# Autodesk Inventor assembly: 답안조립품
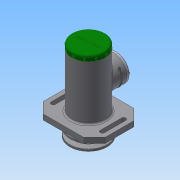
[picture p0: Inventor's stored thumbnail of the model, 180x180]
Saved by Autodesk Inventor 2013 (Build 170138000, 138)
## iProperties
Created: 2017-10
Part Number: 답안조립품
Document SubType Name: Assembly
Designer: Administrator
Author: Administrator
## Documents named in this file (20)
- C:\Users\Administrator\Desktop\471008V1015\답안조립품.iam
- C:\Users\Administrator\Desktop\471008V1015\본체.ipt
- C:\Users\Administrator\Desktop\471008V1015\V-벨트풀리.ipt
- C:\Users\Administrator\Desktop\471008V1015\너트 M10.ipt
- C:\Users\Administrator\Desktop\471008V1015\멈춤링 15 x 1.ipt
- C:\Users\Administrator\Desktop\471008V1015\멈춤링 35x1.6.ipt
- C:\Users\Administrator\Desktop\471008V1015\베어링 15 x 35 x 11.ipt
- C:\Users\Administrator\Desktop\471008V1015\볼트 M4 x 10.ipt
- C:\Users\Administrator\Desktop\471008V1015\부시1.ipt
- C:\Users\Administrator\Desktop\471008V1015\부시2.ipt
- C:\Users\Administrator\Desktop\471008V1015\사이드 커버.ipt
- 사이드 커버.ipt
- C:\Users\Administrator\Desktop\471008V1015\십자볼트 M3 x 10.ipt
- C:\Users\Administrator\Desktop\471008V1015\오일 실 15 25 7.ipt
- C:\Users\Administrator\Desktop\471008V1015\와셔 3x6.ipt
- C:\Users\Administrator\Desktop\471008V1015\와셔 4x16.ipt
- C:\Users\Administrator\Desktop\471008V1015\와셔 10x21.ipt
- C:\Users\Administrator\Desktop\471008V1015\축.ipt
- C:\Users\Administrator\Desktop\471008V1015\키 4 x 4 x 18.ipt
- C:\Users\Administrator\Desktop\471008V1015\탑 커버.ipt
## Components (2 placed, 2 different names)
1. V-벨트풀리:1
2. ISO 4017 M4 x 10:1
